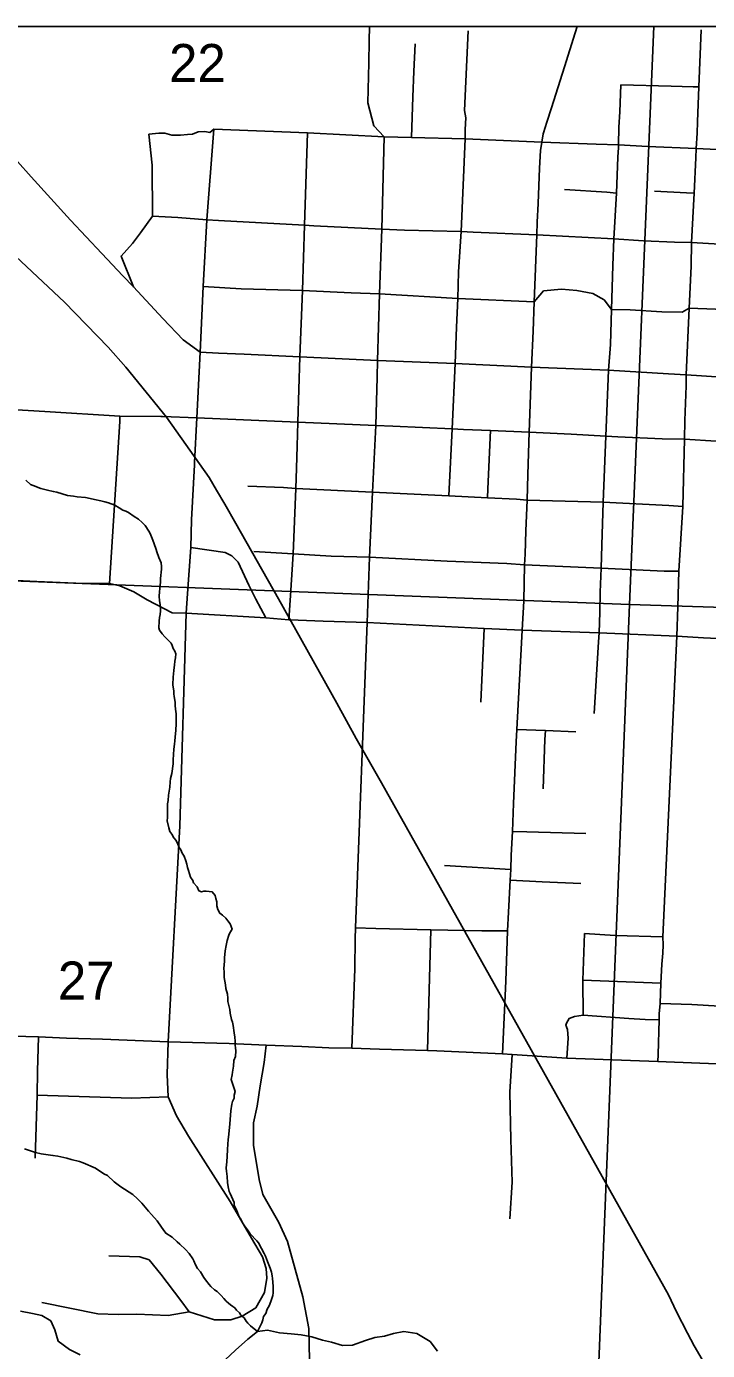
# Model space of a CAD drawing. Extents: x 0 to 34, y 0 to 22.
# Drawn here: x 2.791 to 3.539, y 18.782 to 20.236 of the extents above; entities that cross this region are included whole.
import ezdxf

# ---------------------------------------------------------------- set-up
doc = ezdxf.new("R2010")
doc.units = 0
for name, color, linetype in [('Default', 7, 'Continuous'), ('GM_X_City_Street', 7, 'Continuous'), ('GM_X_County_Road', 7, 'Continuous'), ('GM_X_Minor_River', 7, 'Continuous'), ('GM_X_Rail_Line', 7, 'Continuous'), ('GM_X_Section', 7, 'Continuous'), ('GM_X_Section_Text', 7, 'Continuous'), ('GM_X_State_Route', 7, 'Continuous'), ('GM_X_Township_Road', 7, 'Continuous'), ('GM_X_US_Route', 7, 'Continuous'), ('SH_Border', 7, 'Continuous')]:
    doc.layers.add(name, color=color, linetype=linetype)

msp = doc.modelspace()

# ---------------------------------------------------------------- linework, layer by layer
at = {"layer": 'Default'}
msp.add_lwpolyline([(5.4689, 20.2361), (2, 20.2361), (2, 17.6421), (2.2216, 17.6325), (2.3671, 17.6262), (2.4948, 17.6206), (2.8455, 17.6056), (3.1573, 17.5966), (3.3814, 17.5893), (3.5076, 17.5883), (3.5149, 17.5866), (3.5264, 17.5861), (3.588, 17.5843), (3.668, 17.582), (3.8113, 17.5777), (3.8971, 17.5752), (4.0148, 17.5719), (4.0645, 17.5699), (4.154, 17.5682), (4.2956, 17.5637), (4.3711, 17.5613), (4.4307, 17.5594)], dxfattribs=at)
for points in [[(3.4802, 20.2361), (2.483, 20.2361), (2.4603, 19.6394), (3.4534, 19.6013)], [(4.4834, 20.2361), (3.4802, 20.2361), (3.4534, 19.6013), (4.4585, 19.5694)]]:
    msp.add_lwpolyline(points, close=True, dxfattribs=at)
at = {"layer": 'GM_X_City_Street'}
for p, q in [((2.9717, 19.6637), (3.0093, 19.6585)), ((3.29, 19.4939), (3.2938, 19.575)), ((3.4144, 19.4814), (3.4194, 19.5603)), ((3.25, 19.3145), (3.3229, 19.3101)), ((3.2313, 19.1113), (3.2353, 19.244)), ((3.402, 19.1885), (3.4879, 19.1854))]:
    msp.add_line(p, q, dxfattribs=at)
for points in [[(3.2728, 20.1213), (3.2729, 20.123), (3.2735, 20.1358), (3.2721, 20.144), (3.276, 20.2313)], [(3.5267, 20.1021), (3.5276, 20.1191), (3.5281, 20.1314), (3.5296, 20.1697), (3.5322, 20.2325)], [(3.214, 20.1141), (3.2155, 20.1589), (3.2165, 20.1868), (3.2179, 20.2172)], [(3.4411, 20.1031), (3.4413, 20.106), (3.4416, 20.1255), (3.4426, 20.1422), (3.4438, 20.172)], [(3.4438, 20.172), (3.4992, 20.1707), (3.5233, 20.1697), (3.5296, 20.1697)], [(2.9254, 20.118), (2.9365, 20.1189), (2.9428, 20.1189), (2.9508, 20.1167), (2.9602, 20.1168), (2.968, 20.1176), (2.9732, 20.118), (2.9795, 20.1204), (2.9868, 20.1209), (2.9924, 20.1198), (2.9969, 20.1234)], [(2.9293, 20.0279), (2.9291, 20.0839), (2.9254, 20.118)], [(2.9819, 19.8784), (2.985, 19.9505), (2.9891, 20.0236), (2.9966, 20.1187), (2.9969, 20.1234)], [(2.9969, 20.1234), (3.0997, 20.1192), (3.184, 20.1148), (3.214, 20.1141), (3.2727, 20.1126), (3.3572, 20.109)], [(3.0891, 19.8016), (3.0912, 19.8733), (3.0943, 19.9461), (3.0964, 20.018), (3.0997, 20.1192)], [(3.2617, 19.8661), (3.2633, 19.9058), (3.2648, 19.9372), (3.2654, 19.9667), (3.2683, 20.0108), (3.2727, 20.1126), (3.2728, 20.1213)], [(3.3572, 20.109), (3.4168, 20.1069), (3.4413, 20.106), (3.4734, 20.1043), (3.5267, 20.1021), (3.6103, 20.0982), (3.6275, 20.0973), (3.6489, 20.097), (3.6899, 20.0957), (3.7708, 20.0927)], [(3.4301, 19.8586), (3.4324, 19.8868), (3.4335, 19.9253), (3.4351, 19.9734), (3.4363, 20.0029), (3.4389, 20.0531), (3.4405, 20.0926), (3.4411, 20.1031)], [(3.5139, 19.7827), (3.5142, 19.8035), (3.5157, 19.8413), (3.5157, 19.8533), (3.519, 19.9268), (3.5211, 19.9728), (3.5213, 19.9988), (3.5243, 20.0531), (3.5263, 20.0918), (3.5267, 20.1021)], [(3.3819, 20.0569), (3.4285, 20.0542), (3.4389, 20.0531)], [(3.4807, 20.0552), (3.5161, 20.0535), (3.5243, 20.0531)], [(2.9086, 19.9501), (2.8949, 19.984), (2.9073, 19.9977), (2.9162, 20.0095), (2.9293, 20.0279), (2.9573, 20.0264), (2.9891, 20.0236), (3.0018, 20.0229), (3.0964, 20.018), (3.1068, 20.0171), (3.1814, 20.0136), (3.2061, 20.0124), (3.2683, 20.0108), (3.2816, 20.0103), (3.3515, 20.0073)], [(3.3515, 20.0073), (3.4363, 20.0029), (3.4688, 20.0008), (3.5028, 19.9991), (3.5213, 19.9988), (3.5651, 19.9963), (3.606, 19.9946), (3.6265, 19.9933), (3.667, 19.9917), (3.6863, 19.9909), (3.763, 19.9871)], [(2.985, 19.9505), (3.0269, 19.948), (3.0943, 19.9461), (3.1476, 19.9437), (3.1787, 19.9423), (3.2648, 19.9372), (3.3485, 19.9337)], [(3.3485, 19.9337), (3.359, 19.9456), (3.3788, 19.9474), (3.3956, 19.9461), (3.4132, 19.9429), (3.4255, 19.9359), (3.4335, 19.9253), (3.4542, 19.9247), (3.4887, 19.9227), (3.5113, 19.9222), (3.519, 19.9268), (3.5478, 19.9257), (3.5688, 19.9251), (3.6022, 19.9248), (3.6837, 19.9211), (3.7179, 19.9197), (3.736, 19.9194), (3.7598, 19.9192)], [(3.4301, 19.8586), (3.4962, 19.8547), (3.5157, 19.8533), (3.5546, 19.8511), (3.5823, 19.8506), (3.6004, 19.8502), (3.6794, 19.8466), (3.715, 19.845), (3.7563, 19.8429)], [(2.8821, 19.6241), (2.8935, 19.8024), (2.8936, 19.8082)], [(3.0791, 19.5845), (3.0809, 19.6112), (3.084, 19.657), (3.0869, 19.7288), (3.0877, 19.7508), (3.0885, 19.7753), (3.0891, 19.8016)], [(3.2973, 19.7185), (3.2977, 19.7283), (3.3005, 19.7923)], [(3.5054, 19.5664), (3.5066, 19.5985), (3.5075, 19.6377), (3.5119, 19.709), (3.5139, 19.7827)], [(3.0342, 19.7311), (3.0734, 19.7296), (3.0869, 19.7288), (3.1711, 19.7246)], [(3.4194, 19.5603), (3.42, 19.5701), (3.4206, 19.5927), (3.4213, 19.6147), (3.4222, 19.6412), (3.4228, 19.6665), (3.4244, 19.7137)], [(3.4244, 19.7137), (3.4965, 19.7098), (3.5119, 19.709)], [(3.0538, 19.5864), (3.043, 19.6071), (3.0354, 19.6226), (3.0234, 19.6478), (3.0166, 19.6546), (3.0093, 19.6585)], [(3.0407, 19.6596), (3.084, 19.657), (3.1258, 19.6544), (3.1678, 19.6533), (3.2529, 19.6488), (3.3187, 19.6463), (3.3381, 19.6449)], [(3.3381, 19.6449), (3.4222, 19.6412), (3.4914, 19.6378), (3.5075, 19.6377)], [(2.9557, 19.0396), (2.9467, 19.0603), (2.9456, 19.0848), (2.9466, 19.1209), (2.9595, 19.358), (2.9664, 19.5916)], [(3.4846, 19.0994), (3.485, 19.107), (3.4861, 19.145), (3.486, 19.1514), (3.487, 19.1631), (3.4879, 19.1854), (3.489, 19.2061), (3.4898, 19.2183), (3.4902, 19.2275), (3.49, 19.2361), (3.5054, 19.5664)], [(3.3295, 19.4639), (3.3609, 19.4627), (3.3945, 19.4612)], [(3.3585, 19.3988), (3.3604, 19.4528), (3.3609, 19.4627)], [(3.325, 19.352), (3.3405, 19.3516), (3.4052, 19.3497)], [(3.3224, 19.2985), (3.3573, 19.2965), (3.3999, 19.2949)], [(3.1523, 19.2459), (3.1747, 19.2454), (3.2353, 19.244), (3.2911, 19.2429), (3.3194, 19.2426)], [(3.4023, 19.15), (3.402, 19.1885), (3.4039, 19.2398)], [(3.4039, 19.2398), (3.4377, 19.2378), (3.49, 19.2361)], [(3.487, 19.1631), (3.5218, 19.1617), (3.5834, 19.1583)], [(3.3844, 19.1029), (3.3859, 19.1248), (3.3851, 19.1343), (3.3835, 19.139), (3.3842, 19.1413), (3.387, 19.1466), (3.3928, 19.1488), (3.4023, 19.15), (3.4526, 19.1466), (3.4704, 19.1455), (3.4861, 19.145)], [(2.8007, 18.9932), (2.8026, 19.0621), (2.8033, 19.0887), (2.8043, 19.1262)], [(3.3219, 18.9265), (3.3243, 18.9667), (3.3231, 19.0136), (3.3218, 19.0656), (3.3246, 19.1069)], [(2.8026, 19.0621), (2.9065, 19.059), (2.9467, 19.0603)], [(3.0382, 18.9052), (3.0357, 18.9096), (3.0146, 18.9454), (2.969, 19.0172), (2.9557, 19.0396)], [(3.0429, 18.8288), (3.0526, 18.8456), (3.0551, 18.8613), (3.0542, 18.8718), (3.0501, 18.8848), (3.0382, 18.9052)], [(2.8814, 18.8858), (2.9155, 18.8846), (2.9256, 18.8815), (2.9386, 18.8658), (2.9607, 18.8366), (2.9696, 18.8242)], [(2.8078, 18.8346), (2.8693, 18.8221), (2.8919, 18.8214), (2.9123, 18.8216), (2.9466, 18.8203), (2.9696, 18.8242), (2.9975, 18.8153), (3.0154, 18.8153), (3.0279, 18.8195), (3.0429, 18.8288)]]:
    msp.add_lwpolyline(points, dxfattribs=at)
at = {"layer": 'GM_X_County_Road'}
for p, q in [((3.1673, 20.2203), (3.1678, 20.2361)), ((2.9664, 19.5916), (2.968, 19.6132))]:
    msp.add_line(p, q, dxfattribs=at)
for points in [[(3.184, 20.1148), (3.1725, 20.1271), (3.1659, 20.1523), (3.1671, 20.1961), (3.1673, 20.2203)], [(3.1767, 19.8691), (3.1787, 19.9423), (3.1814, 20.0136), (3.184, 20.1148)], [(2.0942, 19.9914), (2.1599, 19.9484), (2.2416, 19.8949), (2.2943, 19.8605), (2.312, 19.8525), (2.3216, 19.8496), (2.3502, 19.8463), (2.4418, 19.8327), (2.5007, 19.8275), (2.6097, 19.8225), (2.7437, 19.8171), (2.8113, 19.8132), (2.8936, 19.8082), (2.9385, 19.8076)], [(2.9754, 19.7546), (2.9755, 19.7571), (2.9781, 19.8063), (2.9819, 19.8784)], [(3.1767, 19.8691), (3.2617, 19.8661), (3.3456, 19.8619), (3.4301, 19.8586)], [(3.2548, 19.7204), (3.2586, 19.7941), (3.2617, 19.8661)], [(3.4244, 19.7137), (3.4272, 19.7862), (3.4301, 19.8586)], [(2.9385, 19.8076), (2.9405, 19.8076), (2.9781, 19.8063)], [(2.9781, 19.8063), (3.0891, 19.8016), (3.1747, 19.7978)], [(3.1651, 19.5815), (3.1678, 19.6533), (3.1711, 19.7246), (3.1747, 19.7978)], [(2.968, 19.6132), (2.9717, 19.6637), (2.9721, 19.6942), (2.9754, 19.7546)], [(3.1711, 19.7246), (3.2548, 19.7204), (3.2973, 19.7185), (3.3291, 19.7169), (3.341, 19.7159), (3.4244, 19.7137)], [(2.1338, 19.6553), (2.2491, 19.6487), (2.307, 19.6479), (2.4221, 19.6436), (2.6338, 19.6327), (2.7489, 19.629), (2.8023, 19.6265), (2.8537, 19.6242), (2.8821, 19.6241), (2.8934, 19.6218), (2.9089, 19.6153), (2.9235, 19.6063), (2.951, 19.592), (2.9664, 19.5916)], [(2.9664, 19.5916), (3.0538, 19.5864), (3.0791, 19.5845), (3.0801, 19.5844)], [(3.0801, 19.5844), (3.1169, 19.5828), (3.1651, 19.5815), (3.2938, 19.575), (3.3354, 19.573)], [(3.1482, 19.1137), (3.1517, 19.2011), (3.152, 19.2341), (3.1523, 19.2459), (3.1651, 19.5815)], [(3.3354, 19.573), (3.42, 19.5701), (3.5054, 19.5664), (3.5347, 19.5645), (3.6706, 19.5579), (3.8402, 19.5516), (3.8622, 19.551), (3.9502, 19.5484), (3.9645, 19.5475)], [(2.4385, 19.1288), (2.475, 19.1347), (2.4962, 19.1359), (2.5151, 19.1361), (2.5457, 19.1355), (2.5958, 19.1335), (2.6428, 19.1316), (2.685, 19.1303), (2.7343, 19.1285), (2.7764, 19.127), (2.8043, 19.1262), (2.8348, 19.1247), (2.8745, 19.1238), (2.9195, 19.1219), (2.9466, 19.1209), (3.0137, 19.1191), (3.0544, 19.1172)], [(3.0544, 19.1172), (3.0936, 19.1156), (3.1232, 19.1144), (3.1482, 19.1137)], [(3.1482, 19.1137), (3.1789, 19.1129), (3.2313, 19.1113)], [(3.2313, 19.1113), (3.2417, 19.1108), (3.3137, 19.1075)], [(3.3137, 19.1075), (3.3246, 19.1069), (3.3844, 19.1029), (3.4846, 19.0994), (3.5307, 19.0975), (3.6075, 19.0944), (3.6464, 19.0923), (3.6621, 19.0917), (3.7977, 19.0861), (3.8108, 19.0852), (3.8216, 19.0847), (3.9243, 19.0799), (3.9457, 19.0796), (3.959, 19.0827)]]:
    msp.add_lwpolyline(points, dxfattribs=at)
at = {"layer": 'GM_X_Minor_River'}
for points in [[(2.9537, 19.5346), (2.9539, 19.5388), (2.9547, 19.5426), (2.9549, 19.5471), (2.9538, 19.5498), (2.952, 19.5529), (2.951, 19.556), (2.9499, 19.5587), (2.9429, 19.5658), (2.94, 19.569), (2.9371, 19.5729), (2.9364, 19.5756), (2.9366, 19.5828), (2.9372, 19.587), (2.938, 19.5904), (2.9382, 19.5942), (2.9383, 19.5984), (2.938, 19.601), (2.937, 19.6057), (2.9368, 19.6099), (2.9373, 19.6155), (2.9374, 19.6186), (2.9381, 19.6262), (2.9382, 19.6296), (2.9393, 19.6399), (2.9394, 19.6429), (2.9388, 19.6471), (2.9363, 19.6529), (2.9342, 19.6591), (2.9336, 19.6618), (2.9311, 19.668), (2.9297, 19.6718), (2.9269, 19.6792), (2.9254, 19.6819), (2.9215, 19.6881), (2.9181, 19.6913), (2.9141, 19.6948), (2.9092, 19.698), (2.9032, 19.7021), (2.9002, 19.7037), (2.8968, 19.705), (2.8927, 19.7074), (2.8879, 19.7102), (2.8811, 19.7127), (2.8769, 19.714), (2.8728, 19.7149), (2.8656, 19.7167), (2.861, 19.7176), (2.8557, 19.7186), (2.8466, 19.7196), (2.8428, 19.7201), (2.836, 19.7211), (2.8243, 19.7246), (2.8205, 19.7255), (2.8141, 19.7269), (2.8069, 19.7286), (2.7982, 19.732), (2.7956, 19.7332), (2.7904, 19.7376)], [(3.0159, 19.0795), (3.0169, 19.0844), (3.0174, 19.0874), (3.0183, 19.0942), (3.0189, 19.1003), (3.0206, 19.1048), (3.0208, 19.1109), (3.0205, 19.1144), (3.0202, 19.117), (3.0204, 19.1216), (3.0198, 19.1258), (3.0192, 19.1308), (3.0179, 19.1388), (3.0173, 19.1423), (3.0162, 19.1454), (3.0146, 19.1523), (3.0143, 19.1565), (3.0123, 19.1653), (3.0121, 19.1687), (3.0118, 19.1733), (3.0101, 19.1795), (3.0095, 19.1833), (3.0089, 19.1875), (3.0082, 19.1914), (3.0083, 19.194), (3.0081, 19.1978), (3.0078, 19.2013), (3.0085, 19.2093), (3.0086, 19.2134), (3.0087, 19.2169), (3.0092, 19.2207), (3.0102, 19.2267), (3.0115, 19.232), (3.0132, 19.238), (3.0145, 19.2407), (3.0169, 19.2444), (3.0148, 19.2506), (3.0122, 19.2537), (3.01, 19.2568), (3.0063, 19.26), (3.0033, 19.262), (3.0012, 19.2663), (3.0002, 19.2701), (3, 19.2747), (2.9989, 19.2782), (2.9983, 19.2816), (2.995, 19.2855), (2.9885, 19.2865), (2.9858, 19.2862), (2.9832, 19.2856), (2.9805, 19.2868), (2.9784, 19.2911), (2.9743, 19.2954), (2.9737, 19.2981), (2.9711, 19.3016), (2.9691, 19.3089), (2.9677, 19.3124), (2.967, 19.3158), (2.966, 19.3197), (2.9642, 19.3247), (2.9621, 19.3282), (2.9607, 19.3317), (2.9589, 19.3344), (2.9574, 19.3379), (2.9553, 19.3418), (2.9527, 19.3449), (2.9506, 19.3488), (2.9484, 19.3519), (2.9474, 19.3558), (2.9457, 19.3634), (2.9458, 19.3672), (2.9458, 19.3768), (2.946, 19.3821), (2.9465, 19.3859), (2.947, 19.3916), (2.9485, 19.4007), (2.949, 19.4064), (2.9492, 19.4102), (2.9505, 19.4155), (2.952, 19.4261), (2.9521, 19.4306), (2.9529, 19.4424), (2.9535, 19.4477), (2.954, 19.4515), (2.9546, 19.4595), (2.9551, 19.4629), (2.9554, 19.4705), (2.9555, 19.4747), (2.9553, 19.4782), (2.9554, 19.4812), (2.9548, 19.4862), (2.9545, 19.4904), (2.9543, 19.4938), (2.9533, 19.5003), (2.9527, 19.503), (2.9528, 19.5061), (2.9518, 19.5129), (2.9521, 19.5217), (2.9526, 19.5247), (2.9528, 19.5289), (2.9537, 19.5346)], [(3.0159, 19.0795), (3.0203, 19.0662), (3.019, 19.0621), (3.019, 19.0591), (3.0174, 19.0553), (3.0165, 19.0523), (3.0156, 19.0451), (3.0146, 19.0356), (3.0145, 19.0307), (3.0131, 19.0193), (3.0126, 19.0133), (3.0121, 19.0087), (3.0119, 19.0023), (3.0109, 18.9886), (3.0108, 18.986), (3.0103, 18.9822), (3.0106, 18.9787), (3.0113, 18.973), (3.0119, 18.9662), (3.0125, 18.9616), (3.0136, 18.9566), (3.0146, 18.9543), (3.0161, 18.9509), (3.019, 18.9444), (3.0193, 18.9409), (3.0215, 18.9371), (3.0247, 18.9286), (3.0265, 18.9259), (3.0291, 18.9209), (3.0305, 18.9186), (3.0339, 18.9144), (3.0368, 18.9101), (3.0442, 18.9023), (3.0457, 18.9), (3.049, 18.8939), (3.0519, 18.8885), (3.0534, 18.8854), (3.0559, 18.8796), (3.0588, 18.8723), (3.0602, 18.8677), (3.0608, 18.8639), (3.0611, 18.8609), (3.0621, 18.8525), (3.0619, 18.8453), (3.0615, 18.8423), (3.0602, 18.8377), (3.0594, 18.8355), (3.0574, 18.831), (3.0554, 18.8272), (3.0538, 18.8223), (3.0514, 18.819), (3.0506, 18.8156), (3.0494, 18.8122), (3.0449, 18.8025)], [(2.876, 18.976), (2.867, 18.9819), (2.8534, 18.988), (2.8493, 18.9892), (2.8402, 18.9917), (2.8353, 18.993), (2.8254, 18.9951), (2.8201, 18.996), (2.8073, 18.9979), (2.8008, 18.9992), (2.7887, 19.0033)], [(3.0449, 18.8025), (3.0371, 18.8087), (3.0342, 18.8118), (3.0323, 18.8141), (3.0301, 18.8176), (3.0264, 18.8207), (3.0249, 18.823), (3.0216, 18.8262), (3.0197, 18.8285), (3.0175, 18.8301), (3.0152, 18.832), (3.013, 18.8336), (3.0104, 18.8359), (3.0078, 18.839), (3.0048, 18.8422), (3.0003, 18.8464), (2.9974, 18.8484), (2.9936, 18.8519), (2.9918, 18.8543), (2.9877, 18.8593), (2.9859, 18.862), (2.9822, 18.8682), (2.9789, 18.8717), (2.9767, 18.8759), (2.9749, 18.8801), (2.9738, 18.8824), (2.9698, 18.8882), (2.9657, 18.8929), (2.9593, 18.8987), (2.9567, 18.9011), (2.9512, 18.9062), (2.944, 18.9105), (2.9411, 18.9148), (2.9392, 18.9171), (2.9345, 18.9241), (2.9285, 18.931), (2.9252, 18.9349), (2.9178, 18.9435), (2.913, 18.9485), (2.9078, 18.9532), (2.8946, 18.9615), (2.8872, 18.967), (2.8801, 18.974), (2.876, 18.976)], [(2.8499, 18.7769), (2.8382, 18.7829), (2.8259, 18.7919), (2.8221, 18.8045), (2.8178, 18.8142), (2.808, 18.8201), (2.7975, 18.8226), (2.7846, 18.8248)], [(3.2426, 18.7812), (3.2345, 18.7916), (3.2198, 18.8006), (3.2055, 18.8027), (3.194, 18.8006), (3.1841, 18.7974), (3.1738, 18.7961), (3.1635, 18.7928), (3.149, 18.7878), (3.138, 18.7872), (3.1259, 18.7908), (3.1161, 18.7933), (3.1044, 18.7969), (3.0927, 18.799), (3.0817, 18.8), (3.0688, 18.8013), (3.0556, 18.8042), (3.0449, 18.8025), (3.0342, 18.7944), (3.0206, 18.7821), (3.0094, 18.7716)]]:
    msp.add_lwpolyline(points, dxfattribs=at)
at = {"layer": 'GM_X_Rail_Line'}
msp.add_lwpolyline([(2.5076, 20.2361), (2.5238, 20.2211), (2.6148, 20.1368), (2.7315, 20.028), (2.8329, 19.9334), (2.8809, 19.884), (2.9003, 19.862), (2.9449, 19.8071), (2.9917, 19.7407), (2.9999, 19.7269), (3.0087, 19.7113), (3.0209, 19.6901), (3.0679, 19.6073), (3.1318, 19.4927), (3.1532, 19.4542), (3.181, 19.4052), (3.4963, 18.8429), (3.5051, 18.8241), (3.5169, 18.8009), (3.5243, 18.7869), (3.5383, 18.7631)], dxfattribs=at)
at = {"layer": 'GM_X_Section'}
for points in [[(2.4603, 19.6394), (3.4534, 19.6013), (3.4129, 18.6059), (2.4184, 18.643)], [(3.4534, 19.6013), (4.4585, 19.5694), (4.4175, 18.5694), (3.4129, 18.6059)]]:
    msp.add_lwpolyline(points, close=True, dxfattribs=at)
at = {"layer": 'GM_X_State_Route'}
for points in [[(3.3587, 20.1183), (3.3588, 20.1192), (3.3626, 20.1311), (3.3676, 20.1467), (3.3818, 20.1919), (3.3938, 20.2293), (3.3959, 20.2361)], [(3.3433, 19.7904), (3.3456, 19.8619), (3.3475, 19.9016), (3.3485, 19.9337), (3.3515, 20.0073), (3.3521, 20.0213), (3.353, 20.0418), (3.3545, 20.0804), (3.3557, 20.1), (3.3572, 20.109), (3.3587, 20.1183)], [(3.3137, 19.1075), (3.3174, 19.1875), (3.3194, 19.2426), (3.3203, 19.2632), (3.3224, 19.2985), (3.3229, 19.3101), (3.3233, 19.3257), (3.325, 19.352), (3.3259, 19.3828), (3.3287, 19.4505), (3.3295, 19.4639), (3.3321, 19.5117), (3.3342, 19.5522), (3.3354, 19.573), (3.3372, 19.6049), (3.3381, 19.6449), (3.3388, 19.6564), (3.3393, 19.6821), (3.341, 19.7159), (3.3416, 19.7441), (3.3433, 19.7904)], [(3.3433, 19.7904), (3.3893, 19.7883), (3.4272, 19.7862)], [(3.4272, 19.7862), (3.4407, 19.7854), (3.4891, 19.7833), (3.5139, 19.7827)], [(3.5139, 19.7827), (3.5486, 19.7807), (3.5783, 19.7798), (3.5984, 19.7789)], [(2.4385, 19.1288), (2.475, 19.1347), (2.4962, 19.1359), (2.5151, 19.1361), (2.5457, 19.1355), (2.5958, 19.1335), (2.6428, 19.1316), (2.685, 19.1303), (2.7343, 19.1285), (2.7764, 19.127), (2.8043, 19.1262), (2.8348, 19.1247), (2.8745, 19.1238), (2.9195, 19.1219), (2.9466, 19.1209), (3.0137, 19.1191), (3.0544, 19.1172)], [(3.0544, 19.1172), (3.0936, 19.1156), (3.1232, 19.1144), (3.1482, 19.1137)], [(3.1482, 19.1137), (3.1789, 19.1129), (3.2313, 19.1113)], [(3.2313, 19.1113), (3.2417, 19.1108), (3.3137, 19.1075)]]:
    msp.add_lwpolyline(points, dxfattribs=at)
at = {"layer": 'GM_X_Township_Road'}
msp.add_lwpolyline([(3.0962, 18.6038), (3.0964, 18.6079), (3.0979, 18.6382), (3.0995, 18.6868), (3.1015, 18.7233), (3.1022, 18.742), (3.102, 18.7713), (3.1011, 18.8059), (3.0945, 18.8406), (3.0778, 18.9015), (3.0681, 18.9223), (3.0505, 18.9531), (3.0467, 18.9695), (3.0402, 19.0073), (3.0405, 19.0319), (3.0444, 19.0501), (3.0476, 19.0726), (3.0519, 19.098), (3.0544, 19.1172)], dxfattribs=at)
at = {"layer": 'GM_X_US_Route'}
msp.add_line((3.1933, 19.797), (3.1747, 19.7978), dxfattribs=at)
for points in [[(3.0019, 19.8774), (2.9819, 19.8784), (2.963, 19.892), (2.9409, 19.9154), (2.9086, 19.9501), (2.8967, 19.9621), (2.8739, 19.9867), (2.8394, 20.0235), (2.7961, 20.071), (2.766, 20.1048), (2.7338, 20.145), (2.7209, 20.1603), (2.701, 20.186), (2.6727, 20.2207), (2.66, 20.2361)], [(3.1767, 19.8691), (3.0912, 19.8733), (3.03, 19.8761), (3.0019, 19.8774)], [(3.1747, 19.7978), (3.1763, 19.8511), (3.1767, 19.8691)], [(3.3433, 19.7904), (3.3005, 19.7923), (3.271, 19.7934), (3.2586, 19.7941), (3.1933, 19.797)], [(3.4272, 19.7862), (3.3893, 19.7883), (3.3433, 19.7904)], [(3.5139, 19.7827), (3.4891, 19.7833), (3.4407, 19.7854), (3.4272, 19.7862)], [(3.5984, 19.7789), (3.5783, 19.7798), (3.5486, 19.7807), (3.5139, 19.7827)]]:
    msp.add_lwpolyline(points, dxfattribs=at)
at = {"layer": 'SH_Border'}
msp.add_lwpolyline([(2, 20.2361), (2, 13.4361), (8.8, 13.4361), (8.8, 20.2361)], close=True, dxfattribs=at)

# ---------------------------------------------------------------- texts
at = {"layer": 'GM_X_Section_Text'}
for s, p in [('22', (2.9476, 20.175)), ('27', (2.8255, 19.1672))]:
    msp.add_text(s, height=0.04186, rotation=0, dxfattribs=at).set_placement(p)

doc.saveas('drawing.dxf')
